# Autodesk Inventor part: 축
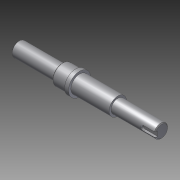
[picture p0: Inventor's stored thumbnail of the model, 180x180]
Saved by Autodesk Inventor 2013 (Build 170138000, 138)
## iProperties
Company: 한국ATC센터
Created: 2014-03
Part Number: 축
Document SubType Name: Modeling
Designer: KYOUNG IL JANG
Density: 1 g/cm^3
Material: 일반
Author: KYOUNG IL JANG
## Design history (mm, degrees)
sketch "스케치1"
  geometry: L1 (-102, 80)-(78, 80); L2 (-30.3, 106)-(-30.3, 54) reference; L3 (23, 99.7)-(23, 60.3) reference; L4 (-102, 80)-(-102, 89); L5 (-102, 89)-(-47, 89); L6 (-47, 89)-(-47, 92.5); L7 (-47, 92.5)-(-30, 92.5); L8 (-25, 94)-(-25, 91); L9 (-25, 91)-(23, 91); L10 (23, 91)-(23, 88.5); L11 (23, 88.5)-(78, 88.5); L12 (78, 88.5)-(78, 80); L13 (-30, 94)-(-25, 94); L14 (-31, 92.5)-(-44, 92.5) reference; L15 (-30, 105)-(-30, 55) reference; L16 (-30, 94)-(-30, 92.5); L17 (-68, 65.3)-(-68, 94.7) reference; L18 (-96, 89)-(-96, 85.5); L19 (-96, 85.5)-(-74, 85.5); L20 (-74, 85.5)-(-74, 89); L21 (60, 75)-(83, 75); L22 (83, 75)-(83, 71.5); L23 (83, 71.5)-(60, 71.5); L24 (60, 71.5)-(60, 75); 2 further points
  constraints: 40 end point, 12 perpendicular, 7 point on line, 3 horizontal, 3 parallel, 2 collinear, 1 midpoint, 1 other
  dimensions: "d0" = 18 diameter of L5 L1; "d1" = 17 distance of L6.end L7.end; "d2" = 5 distance of L13.start L8.start; "d3" = 28 diameter of L13 L1; "d4" = 22 diameter of L9 L1; "d5" = 17 diameter of L11 L1; "d8" = 34 distance between parallel lines of L17 L4; "d9" = 55 distance of L10.end L11.end; "d11" = 3.5 distance between parallel lines of L19 L5; "d12" = 22 distance between parallel lines of L20 L18; "d13" = 6 distance between parallel lines of L18 L4; "d14" = 17 diameter of L23 L1 (= d5); "d15" = 3.5 distance of L23.end L21.start (= d11); "d16" = 18 distance between parallel lines of L24 L12; "d17" = 23 distance of L22.end L23.end
  node "참조1"
  node "참조2"
  node "참조3"
  node "참조4"
revolve "회전1" stored, may be unused: angle "d10" = 90 deg
extrude "돌출1" cut sketch "스케치1" stored distance "d18" = 6; taper "d19" = 0 deg
fillet "모깎기1" dims "d20" = 3
chamfer "모따기1" distance "d21" = 1; stored, may be unused: second distance "d22" = 2, angle "d23" = 45 deg
node "솔리드1"
